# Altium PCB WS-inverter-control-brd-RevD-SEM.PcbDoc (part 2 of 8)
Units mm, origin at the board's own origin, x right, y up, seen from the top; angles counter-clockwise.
Board outline 270 x 105.92 mm, 6 copper layers (Top Layer, Int1 (Sign), Int2 (PWR), Int3 (GND), Int4 (Sign), Bottom Layer), stack 1.509 mm thick; 709 components, 375 nets, 2377 pads, 1332 vias.
Unrouted connection lines stored in the file: 55.
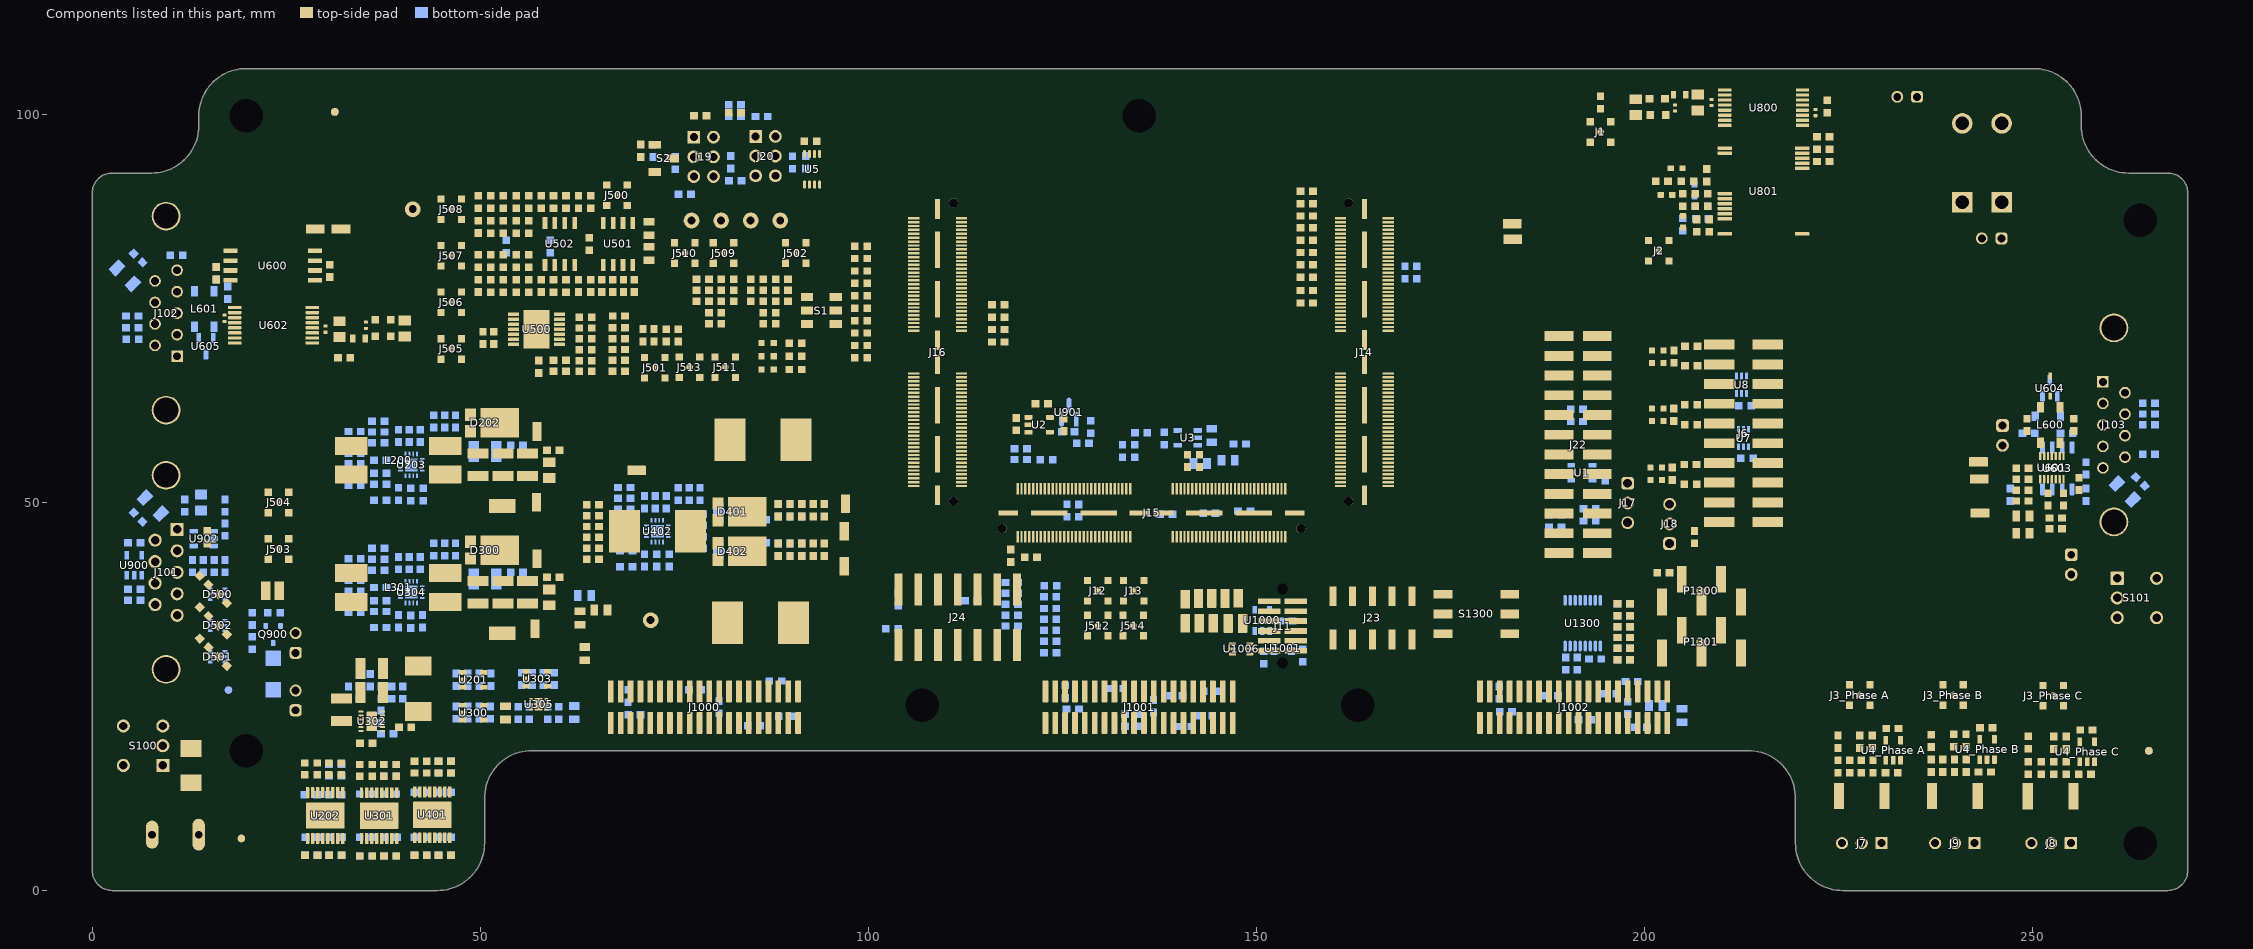
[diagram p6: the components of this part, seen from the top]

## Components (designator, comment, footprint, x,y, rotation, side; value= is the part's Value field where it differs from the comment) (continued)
R557 "CRCW06036K04FKEA" 0603#1 80.25,74.453 r180 top value=6.04k
R558 "CRCW060310K0FKEA" 0603#1 88.85,77.353 r180 top value=10.0k
R559 "CRCW060310K0FKEA" 0603#1 81.85,77.353 r180 top value=10.0k
R560 "CRCW060310K0FKEA" 0603#1 88.85,78.753 r180 top value=10.0k
R561 "CRCW060310K0FKEA" 0603#1 81.85,78.753 r180 top value=10.0k
R562 "CRCW06030000Z0EA" 0603#1 75.521,71.536 r90 top value=0
R563 "CRCW06030000Z0EA" 0603#1 118.468,38.286 r180 bottom value=0
R564 "CRCW06030000Z0EA" 0603#1 118.468,36.886 r0 bottom value=0
R565 "CRCW060347R0FKEA" 0603#1 118.468,35.486 r180 bottom value=47.0
R566 "CRCW06030000Z0EA" 0603#1 70.957,71.557 r90 top value=0
R568 "CRCW06030000Z0EA" 0603#1 191.293,60.436 r0 bottom value=0
R569 "CRCW06030000Z0EA" 0603#1 123.418,33.542 r0 bottom value=0
R570 "CRCW060347R0FKEA" 0603#1 123.443,32.136 r180 bottom value=47.0
R600 "CRCW06030000Z0EA" 0603#2 249.3,60 r90 top value=0
R601 "CRCW06030000Z0EA" 0603#2 17.443,77.036 r270 bottom value=0
R602 "CRCW060360R4FKEA" 0603#2 265,61.406 r180 bottom value=60.4
R603 "CRCW060360R4FKEA" 0603#2 5.168,71.021 r0 bottom value=60.4
R604 "CRCW060310R0FKEA" 0603#2 248.7,53 r0 top value=10.0
R605 "CRCW060360R4FKEA" 0603#2 265,62.806 r0 bottom value=60.4
R606 "CRCW060310K0FKEA" 0603#2 248.7,54.4 r0 top value=10.0k
R607 "CRCW060360R4FKEA" 0603#2 5.143,74.036 r180 bottom value=60.4
R608 "CRCW06030000Z0EA" 0603#2 255.3,60 r90 top value=0
R609 "CRCW060310R0FKEA" 0603#2 248.7,50.2 r0 top value=10.0
R610 "CRCW06030000Z0EA" 0603#2 10.843,81.836 r180 bottom value=0
R612 "CRCW06031K00FKEA" 0603#2 249.5,58.9 r0 bottom value=1.00k
R613 "CRCW060310K0FKEA" 0603#2 256.9,54.4 r90 bottom value=10.0k
R614 "CRCW060310R0FKEA" 0603#2 256.9,51 r90 bottom value=10.0
R615 "CRCW060310R0FKEA" 0603#2 247.15,51 r90 bottom value=10.0
R616 "CRCW060310R0FKEA" 0603#1 147.843,57.536 r0 bottom value=10.0
R617 "CRCW060310K0FKEA" 0603#1 248.7,51.6 r0 top value=10.0k
R618 "CRCW060310K0FKEA" 0603#1 253,46.6 r0 top value=10.0k
R619 "CRCW060310K0FKEA" 0603#1 253,48 r0 top value=10.0k
R620 "RC0603FR-0718KL" 0603#1 32.443,68.636 r0 top value=18.0k
R800 "RC0603FR-0718KL" 0603#1 194.343,101.536 r270 top value=18.0k
R804 "CRCW06030000Z0EA" 0603#1 132.743,56.636 r270 bottom value=0
R900 "CRCW0603100RFKEA" 0603#2 125.743,59.136 r0 bottom value=100
R901 "CRCW060317K8FKEA" 0603#2 17.1,46.5 r90 bottom value=17.8k
R902 "CRCW060330K1FKEA" 0603#2 17.1,49.6 r90 bottom value=30.1k
R903 "CRCW080520K0FKEA" 0805_HV#1 14,50 r270 bottom value=20.0k
R904 "CRCW060347R0FKEA" 0603#2 14.3,41.8 r90 bottom value=47.0
R905 "CRCW060310K0FKEA" 0603#2 20.6,35 r270 bottom value=10.0k
R906 "CRCW0603100RFKEA" 0603#2 20.6,31.9 r90 bottom value=100
R907 "CRCW060310K0FKEA" 0603#2 23.4,35.8 r180 bottom value=10.0k
R1000 "CRCW06030000Z0EA" 0603#2 69.031,25.056 r270 bottom value=0
R1001 "CRCW06030000Z0EA" 0603#2 125.349,25.653 r270 bottom value=0
R1002 "CRCW06030000Z0EA" 0603#2 181.271,25.5 r270 bottom value=0
R1003 "CRCW06030000Z0EA" 0603#2 69.843,22.636 r0 bottom value=0
R1004 "CRCW06030000Z0EA" 0603#2 126.343,23.386 r0 bottom value=0
R1005 "CRCW06030000Z0EA" 0603#2 182.143,23.036 r0 bottom value=0
R1006 "CRCW06030000Z0EA" 0603#2 88.029,26.999 r0 bottom value=0
R1007 "CRCW06030000Z0EA" 0603#2 144.029,25.653 r0 bottom value=0
R1008 "CRCW06030000Z0EA" 0603#2 198.343,26.936 r180 bottom value=0
R1009 "CRCW06030000Z0EA" 0603#2 89.243,22.436 r180 bottom value=0
R1010 "CRCW06030000Z0EA" 0603#2 143.499,22.522 r0 bottom value=0
R1011 "CRCW06030000Z0EA" 0603#2 199.543,21.036 r0 bottom value=0
R1012 "CRCW06030000Z0EA" 0603#1 192.3,22 r0 bottom value=0
R1013 "CRCW06030000Z0EA" 0603#1 80.743,23.636 r90 bottom value=0
R1014 "CRCW06030000Z0EA" 0603#1 136.743,23.736 r90 bottom value=0
R1015 "CRCW06030000Z0EA" 0603#1 133.869,21.145 r180 bottom value=0
R1016 "CRCW06030000Z0EA" 0603#1 133.869,22.717 r0 bottom value=0
R1017 "CRCW06030000Z0EA" 0603#1 139.689,25.117 r0 bottom value=0
R1018 "CRCW06030000Z0EA" 0603#1 195.614,25.362 r0 bottom value=0
R1019 "CRCW060310K0FKEA" 0603#1 77.675,25.855 r0 bottom value=10.0k
R1020 "CRCW060310K0FKEA" 0603#1 132.043,26.036 r180 bottom value=10.0k
R1021 "CRCW060310K0FKEA" 0603#1 188.069,25.1 r180 bottom value=10.0k
R1022 "CRCW060310K0FKEA" 0603#1 85.243,21.236 r0 bottom value=10.0k
R1023 "CRCW060310K0FKEA" 0603#1 140.82,21.13 r0 bottom value=10.0k
R1024 "CRCW060310K0FKEA" 0603#1 197.843,23.536 r270 bottom value=10.0k
R1027 "CRCW060310K0FKEA" 0603#1 138.383,48.491 r0 bottom value=10.0k
R1030 "CRCW060310K0FKEA" 0603#1 143.943,48.636 r0 bottom value=10.0k
R1034 "CRCW06030000Z0EA" 0603#1 116.743,73.884 r0 top value=0
R1036 "CRCW06030000Z0EA" 0603#1 116.743,70.684 r0 top value=0
R1040 "CRCW06030000Z0EA" 0603#1 116.743,75.484 r0 top value=0
R1042 "CRCW06030000Z0EA" 0603#1 116.743,72.284 r0 top value=0
R1300 "CRCW06031K00FKEA" 0603#2 197.343,36.936 r180 top value=1.00k
R1301 "CRCW06031K00FKEA" 0603#2 197.343,35.4 r180 top value=1.00k
R1302 "CRCW06031K00FKEA" 0603#2 197.343,34 r180 top value=1.00k
R1303 "CRCW06031K00FKEA" 0603#2 191.326,29.242 r90 bottom value=1.00k
R1304 "CRCW06030000Z0EA" 0603#2 189.843,29.236 r90 bottom value=0
R1305 "CRCW06031K00FKEA" 0603#2 197.343,29.714 r180 top value=1.00k
R1306 "CRCW06031K00FKEA" 0603#2 197.343,31.2 r180 top value=1.00k
R1307 "CRCW06031K00FKEA" 0603#2 197.343,32.6 r180 top value=1.00k
Rjldc1 "CRCW06030000Z0EA" 0603#1 127.113,48.955 r270 bottom value=0
Rjldc2 "CRCW06030000Z0EA" 0603#1 125.589,48.97 r270 bottom value=0
Rjump12v "5106" 5106#1 62.843,35.136 r270 top value=0
Rjumppre "5106" 5106#1 63.443,38.036 r180 bottom value=0
S1 "CAS-220TA" SW_CAS-220TA 93.943,74.736 r180 top
S2 "CAS-120TA" SW_CAS-120TA 73.643,94.336 r0 top
S100 "200MSP1T1B2M6QE" FP-200MSP1T1B2M6QE_PTH_SW_23MM63_8MM13-MFG -3.185,18.66 r0 top locked
S101 "200MSP1T1B2M6QE" FP-200MSP1T1B2M6QE_PTH_SW_23MM63_8MM13-MFG 273.185,37.696 r180 top locked
S1300 "219-3MST" SW_219-3MST 178.343,35.636 r180 top locked
TP1 "RCU-0C" TE_RCU 140.843,37.536 r90 top
TP2 "RCU-0C" TE_RCU 142.543,37.636 r90 top
TP3 "RCU-0C" TE_RCU 144.243,37.636 r90 top
TP4 "RCU-0C" TE_RCU 145.943,37.636 r90 top
TP5 "RCU-0C" TE_RCU 147.65,37.678 r90 top
TP6 "RCU-0C" TE_RCU 148.23,34.41 r90 top
TP7 "RCU-0C" TE_RCU 146.364,34.415 r90 top
TP8 "RCU-0C" TE_RCU 144.458,34.436 r90 top
TP9 "RCU-0C" TE_RCU 142.643,34.436 r90 top
TP10 "RCU-0C" TE_RCU 140.845,34.426 r90 top
TP100 "5000" Keystone5000 71.943,34.836 r90 top
TP101 "5000" Keystone5000 41.293,87.795 r90 top
TP200 "5015" Testpoint_Keystone_Miniature 52.8,49.55 r0 top
TP201 "RCU-0C" TE_RCU 57.3,59.15 r90 top
TP202 "RCU-0C" TE_RCU 57.243,50.036 r90 top
TP300 "5015" Testpoint_Keystone_Miniature 52.8,33.15 r180 top
TP301 "RCU-0C" TE_RCU 57.3,42.75 r90 top
TP302 "RCU-0C" TE_RCU 57.043,33.736 r90 top
TP400 "RCU-0C" TE_RCU 70.143,54.136 r180 top
TP401 "RCU-0C" TE_RCU 97.043,49.836 r270 top
TP402 "RCU-0C" TE_RCU 96.9,46.3 r90 top
TP403 "RCU-0C" TE_RCU 22.343,38.636 r90 top
TP404 "RCU-0C" TE_RCU 96.9,41.8 r90 top
TP500 "5000" Keystone5000 84.833,86.336 r90 top
TP501 "5000" Keystone5000 77.213,86.336 r90 top
TP502 "5000" Keystone5000 88.643,86.336 r90 top
TP503 "5000" Keystone5000 81.023,86.336 r90 top
TP600 "RCU-0C" TE_RCU 243.143,53.036 r0 top
TP601 "RCU-0C" TE_RCU 32.043,85.236 r180 top
TP602 "RCU-0C" TE_RCU 243.043,55.236 r180 top
TP603 "RCU-0C" TE_RCU 28.743,85.236 r180 top
TP604 "RCU-0C" TE_RCU 243.243,48.636 r0 top
TP900 "RCU-0C" TE_RCU 24.093,38.636 r90 top
TP_alert "RCU-0C" TE_RCU 182.943,85.936 r180 top
TP_voc "RCU-0C" TE_RCU 183.043,83.936 r0 top
U1 "SN74LVC1G3208DBVR" DBV0006A_N 191.943,53.836 r0 bottom
U2 "REF2033AIDDCR" DDC0005A_N 122.01,60.011 r0 top
U3 "TLV9001QDBVRQ1" DBV0005A-MFG 141.143,58.336 r180 bottom
"U4_Phase A" "TLV9001QDBVRQ1" DBV0005A-MFG 232.05,18.078 r90 top (schematic designator U4)
"U4_Phase B" "TLV9001QDBVRQ1" DBV0005A-MFG 244.15,18.178 r90 top (schematic designator U4)
"U4_Phase C" "TLV9001QDBVRQ1" DBV0005A-MFG 257.05,17.878 r90 top (schematic designator U4)
U5 "CLVC2G125IDCTRQ1" DCT0008A_N 92.743,92.936 r270 top
U7 "SN74LVC1G11IDCKRQ1" DCK0006A_N 212.773,58.299 r270 bottom
U8 "SN74LVC1G11IDCKRQ1" DCK0006A_N 212.523,65.174 r270 bottom
U201 "TPS7B6933QDBVRQ1" DBV0005A_N 49.075,27.15 r0 top
U202 "LM74202QPWPRQ1" PWP0016J_N 30,9.663 r90 top
U203 "LM5158QRTERQ1" RTE0016K-MFG 41.1,54.85 r90 bottom
U300 "TPS7B6933QDBVRQ1" DBV0005A_N 49.075,22.925 r0 top
U301 "LM74202QPWPRQ1" PWP0016J_N 36.957,9.643 r90 top
U302 "LM63635DQDRRRQ1" DRR0012E-MFG 36,21.8 r180 top
U303 "TLV73333PQDBVRQ1" DBV0005A_N 57.3,27.275 r0 top
U304 "LM5158QRTERQ1" RTE0016K-MFG 41.1,38.45 r90 bottom
U305 "TLV73333PQDRVRQ1" DRV0006A 57.5,24 r180 top
U401 "LM74202QPWPRQ1" PWP0016J_N 43.8,9.743 r90 top
U402 "LM5157QRTERQ1" RTE0016K 72.8,46.3 r90 bottom
U500 "ALM2403QPWPRQ1" PWP0014H_N 57.238,72.311 r180 top
U501 "OPA2991IDR" D0008A-MFG 67.738,83.311 r90 top
U502 "OPA2991IDR" D0008A-MFG 60.238,83.311 r90 top
U600 "ISO1042QDWVRQ1" DWV0008A-MFG 23.243,80.536 r180 top
U601 "TCAN1043ADYYRQ1" DYY0014A-MFG 252.5,54.5 r90 top
U602 "UCC33421-Q1" DWX0016A-MFG 23.343,72.836 r180 top
U603 "TLIN1021ADRQ1" D0008A-MFG 253.2,54.4 r90 bottom
U604 "ESD2CAN24DBZR" DBZ0003A-MFG 252.243,64.736 r90 bottom
U605 "ESD2CAN24DBZR" DBZ0003A-MFG 14.643,70.136 r270 bottom
U800 "UCC33421-Q1" DWX0016A-MFG 215.35,100.878 r0 top
U801 "AMC038x" DFX0015-MFG 215.343,90.136 r180 top
U900 "TPS7B4255QDBVRQ1" DBV0005A-MFG 5.4,41.9 r90 bottom
U901 "TMP235AEDBZRQ1" FP-DBZ0003A-IPC_A 125.843,61.636 r90 bottom
U902 "TLV9001QDBVRQ1" DBV0005A-MFG 14.343,45.353 r180 bottom
U1000 "SN74AHC1G32DBVR" DBV0005A_N 150.744,34.813 r90 bottom
U1001 "SN74LVC1G332DCKR" DCK0006A_N 153.394,31.188 r0 bottom
U1006 "SN74LVC1G332DCKR" DCK0006A_N 148.043,31.136 r180 top
U1300 "TXB0106PWR" PW0016A_N 192.05,34.45 r90 bottom

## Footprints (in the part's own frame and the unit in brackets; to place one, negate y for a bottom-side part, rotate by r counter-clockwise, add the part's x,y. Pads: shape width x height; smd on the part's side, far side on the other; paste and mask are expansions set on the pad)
0603#1 [mm] "0603 from SM-752 data"
  rect 1x0.95 smd: 1(-0.8,0) 2(0.8,0)
  silkscreen extent -1.52,-0.69 1.52,0.69, body extent -0.87,-0.47 0.87,0.47, height 1
0603#2 [mm] "0603 from SM-752 data"
  rrect1% 1x0.95 smd: 1(-0.8,0) 2(0.8,0)
  silkscreen extent -1.52,-0.69 1.52,0.69, body extent -0.87,-0.47 0.87,0.47, height 1
0805_HV#1 [mil] "0805 with 30mil clearance between pads"
  rrect1% 50x63 smd: 1(-40,0) 2(40,0)
  silkscreen extent -74,-40 74,40, body extent -43,-29 43,29, height 57
0805_HV#2 [mil] "0805 with 30mil clearance between pads"
  rect 50x63 smd: 1(-40,0) 2(40,0)
  silkscreen extent -74,-40 74,40, body extent -43,-29 43,29, height 57
1206 [mm] "1206 from SM-752 data"
  rrect1% 1.3x1.85 smd: 1(-1.45,0) 2(1.45,0)
  silkscreen extent -2.4,-1.21 2.4,1.21, body extent -1.7,-0.9 1.7,0.9, height 1.35
1206_190 [mm] "1206_190"
  rrect1% 1.1x1.6 smd: 1(-1.7,0) 2(1.7,0)
  silkscreen extent -0.9,-1 0.9,1, body extent -1.75,-0.95 1.75,0.95, height 1.9
1210 [mm] "1210 from SM-752 data"
  rrect1% 1.3x2.7 smd: 1(-1.45,0) 2(1.45,0)
  silkscreen extent -2.32,-1.57 2.32,1.57, body extent -1.7,-1.35 1.7,1.35, height 1.35
1210_270#1 [mm] "1210"
  rrect1% 1.3x2.7 smd: 1(-1.45,0) 2(1.45,0)
  silkscreen extent -2.32,-1.57 2.32,1.57, body extent -1.7,-1.35 1.7,1.35, height 2.7
1210_270#2 [mm] "1210"
  rect 1.3x2.7 smd: 1(-1.45,0) 2(1.45,0)
  silkscreen extent -2.32,-1.57 2.32,1.57, body extent -1.7,-1.35 1.7,1.35, height 2.7
2512 [mm] "Chip Resistor, Body 6.3x3.2mm, IPC Medium Density"
  rect 1.3x3.4 smd: 1(-2.95,0) 2(2.95,0)
  silkscreen extent -1.9,-1.6 1.9,1.6, body extent -3.22,-1.67 3.22,1.67, height 0.71
5106#1 [mm] "Keystone"
  rect 0.99x1.4 smd: 1(-0.85,0) 2(0.88,0)
  silkscreen extent -1.63,-0.97 1.65,0.97, body extent -1.06,-0.69 1.06,0.69, height 0.84
5106#2 [mm] "Keystone"
  rrect1% 0.99x1.4 smd: 1(-0.85,0) 2(0.88,0)
  silkscreen extent -1.63,-0.97 1.65,0.97, body extent -1.06,-0.69 1.06,0.69, height 0.84
ACT45B [mm] "SMD, 4-Leads, Body 4.7 x 3.7 mm"
  rrect1% 1.35x0.9 smd: 1(-2.275,1.25) 2(-2.275,-1.25) 3(2.275,-1.25) 4(2.275,1.25)
  silkscreen extent -2.35,-1.7 2.35,2, body extent -2.35,-1.7 2.35,1.7, height 3
CONN_TSM-105-01-T-DV-P [mil]
  rect 36x100 smd: 1(-200,-110) 2(-200,110) 3(-100,-110) 4(-100,110) 5(0,-110) 6(0,110) 7(100,-110) 8(100,110) 9(200,-110) 10(200,110)
  silkscreen extent -250,-160 250,100, body extent -250,-145 250,145, height 380
CUI_PJ-037AH [mm] "Power Jack, 2mm, R/A, TH"
  oval 4.1x1.6 hole 1 slot 3.5 at 0 deg: 1(0,3)
  oval 3.6x1.6 hole 1 slot 3 at 0 deg: 2(0,-3)
  silkscreen extent -4.5,-10.3 4.5,3.8, body extent -4.5,-10.7 4.5,3.8, height 11
D0008A-MFG [mm]
  rrect17% 1.55x0.6 smd paste+0 mask+0: 1(-2.7,1.905) 2(-2.7,0.635) 3(-2.7,-0.635) 4(-2.7,-1.905) 5(2.7,-1.905) 6(2.7,-0.635) 7(2.7,0.635) 8(2.7,1.905)
  silkscreen extent -3.35,-2.5 1.5,3, body extent -3,-2.45 3,2.45, height 1.75
DBV0005A-MFG [mm]
  rrect17% 1.1x0.6 smd paste+0 mask+0: 1(-1.3,0.95) 2(-1.3,0) 3(-1.3,-0.95) 4(1.3,-0.95) 5(1.3,0.95)
  silkscreen extent -0.38,-1.53 0.87,1.53, body extent -1.4,-1.45 1.4,1.45, height 1.45
DBV0005A_N [mm] "SOT23, 5-Leads, Body 2.9x1.6mm, Pitch 0.95mm, Lead Span 2.8mm, IPC Medium Density"
  rrect17% 1x0.6 smd: 1(-1.375,0.95) 2(-1.375,0) 3(-1.375,-0.95) 4(1.375,-0.95) 5(1.375,0.95)
  silkscreen extent -1.63,-1.55 0.38,1.55, body extent -1.42,-1.46 1.42,1.46, height 1.09
DBV0006A_N [mm] "SOT23, 6-Leads, Body 2.9x1.6mm, Pitch 0.95mm, Lead Span 2.8mm, IPC Medium Density"
  rrect17% 1x0.6 smd: 1(-1.375,0.95) 2(-1.375,0) 3(-1.375,-0.95) 4(1.375,-0.95) 5(1.375,0) 6(1.375,0.95)
  silkscreen extent -1.68,-1.55 0.5,1.55, body extent -1.42,-1.46 1.42,1.46, height 1.12
DBZ0003A-MFG [mm]
  rrect17% 1.3x0.6 smd paste+0 mask+0: 1(-1.05,0.95) 2(-1.05,-0.95) 3(1.05,0)
  silkscreen extent -0.7,-1.52 0.7,1.52, body extent -1.18,-1.46 1.18,1.46, height 1.12
DCK0006A_N [mm] "SOT23, 6-Leads, Body 2x1.3mm, Pitch 0.65mm, Lead Span 2.1mm, IPC Medium Density"
  rrect25% 0.85x0.4 smd: 1(-1.125,0.65) 2(-1.125,0) 3(-1.125,-0.65) 4(1.125,-0.65) 5(1.125,0) 6(1.125,0.65)
  silkscreen extent -1.5,-1.09 0.51,1.09, body extent -1.14,-1 1.14,1, height 0.95
DCT0008A_N [mm] "TSOP, 8-Leads, Body 3x2.8mm, Pitch 0.65mm, IPC Medium Density"
  oval 1.05x0.4 smd: 1(-1.975,0.975) 2(-1.975,0.325) 3(-1.975,-0.325) 4(-1.975,-0.975) 5(1.975,-0.975) 6(1.975,-0.325) 7(1.975,0.325) 8(1.975,0.975)
  silkscreen extent -2.32,-1.57 0.6,1.58, body extent -2.01,-1.47 2.01,1.48, height 1.3
DDC0005A_N [mm]
  rrect17% 1x0.6 smd: 1(-1.375,0.95) 2(-1.375,0) 3(-1.375,-0.95) 4(1.375,-0.95) 5(1.375,0.95)
  silkscreen extent -1.25,-1.52 0.88,1.57, body extent -1.41,-1.45 1.41,1.45, height 1.1
DFX0015-MFG [mm]
  rrect22% 1.85x0.45 smd paste+0 mask+0: 1(-4.975,5.525) 2(-4.975,-2.925) 3(-4.975,-3.575) 4(-4.975,-4.225) 5(-4.975,-4.875) 6(-4.975,-5.525) 7(4.975,-5.525) 8(4.975,-4.875) 9(4.975,0.325) 10(4.975,0.975) 11(4.975,1.625) 12(4.975,2.275) 13(4.975,2.925) 14(4.975,3.575) 15(4.975,5.525)
  silkscreen extent -6.58,-6.47 3.5,6.47, body extent -6,-6.72 6,6.72, height 0.25
DRR0012E-MFG [mm]
  rrect40% 0.62x0.25 smd paste+0 mask+0: 1(-1.39,1.25) 2(-1.39,0.75) 3(-1.39,0.25) 4(-1.39,-0.25) 5(-1.39,-0.75) 6(-1.39,-1.25) 7(1.39,-1.25) 8(1.39,-0.75) 9(1.39,-0.25) 10(1.39,0.25) 11(1.39,0.75) 12(1.39,1.25)
  rrect8% 1.3x2.5 smd paste-1000 mask+0: 13(0,0)
  body extent -1.8,-1.65 1.8,1.65, height 0.25
DRV0006A [mm] "SON, 6-Leads, Body 2x2mm, Pitch 0.65mm, Thermal Pad 1.6x1mm, TI Recommended"
  rrect33% 0.45x0.3 smd: 1(-0.975,0.65) 2(-0.975,0) 3(-0.975,-0.65) 4(0.975,-0.65) 5(0.975,0) 6(0.975,0.65)
  rrect14% 1x0.7 on Top Paste: 7(0,0.45) 7(0,-0.45)
  rrect10% 1x1.6 smd paste-0.5: 7(0,0)
  silkscreen extent -1.05,-1.2 1.05,1.2, body extent -1.05,-1.05 1.05,1.05, height 0.81
DWV0008A-MFG [mm]
  rrect17% 1.8x0.6 smd paste+0 mask+0: 1(-5.45,1.905) 2(-5.45,0.635) 3(-5.45,-0.635) 4(-5.45,-1.905) 5(5.45,-1.905) 6(5.45,-0.635) 7(5.45,0.635) 8(5.45,1.905)
  silkscreen extent -5.72,-2.98 3.8,2.98, body extent -6.45,-3.22 6.45,3.22, height 0.25
DWX0016A-MFG [mm]
  rrect24% 1.7x0.41 smd paste+0 mask+0: 1(-5,2.275) 2(-5,1.625) 3(-5,0.975) 4(-5,0.325) 5(-5,-0.325) 6(-5,-0.975) 7(-5,-1.625) 8(-5,-2.275) 9(5,-2.275) 10(5,-1.625) 11(5,-0.975) 12(5,-0.325) 13(5,0.325) 14(5,0.975) 15(5,1.625) 16(5,2.275)
  silkscreen extent -6.53,-2.98 3.8,2.98, body extent -5.95,-3.22 5.95,3.22, height 0.25
DYF0002A-MFG [mm]
  rrect20% 0.9x0.5 smd paste+0 mask+0: 1(-1.3,0) 2(1.3,0)
  silkscreen extent -1.55,-0.7 0.9,0.92, body extent -1.85,-0.8 1.85,0.8, height 0.25
DYY0014A-MFG [mm]
  rrect33% 1.05x0.3 smd paste+0 mask+0: 1(-1.5,1.5) 2(-1.5,1) 3(-1.5,0.5) 4(-1.5,0) 5(-1.5,-0.5) 6(-1.5,-1) 7(-1.5,-1.5) 8(1.5,-1.5) 9(1.5,-1) 10(1.5,-0.5) 11(1.5,0) 12(1.5,0.5) 13(1.5,1) 14(1.5,1.5)
  silkscreen extent -2.72,-2.15 1.05,2.15, body extent -2.12,-2.4 2.12,2.4, height 0.25
FCC_disclaimer [mm]
Fiducial10-20 [mm]
  round 1 smd mask+0.5: 1(0,0)
  Top Layer keep-out circle w1.178: c0,0 r0.5
FP-200MSP1T1B2M6QE_PTH_SW_23MM63_8MM13-MFG [mm]
  rrect6% 1.69x1.69 hole 1.09 paste-2539.97 mask+0: 1(12.265,-2.54)
  round 1.69 hole 1.09 paste-2539.97 mask+0: 2(12.265,0) 3(12.265,2.54) 4(7.185,2.54) 5(7.185,-2.54)
  silkscreen extent 4.23,-4.19 13.79,4.19, body extent -12.29,-4.29 13.21,4.29, height 0.25
FP-06035C100KAT2A_0603-MFG [mm]
  rrect13% 0.8x0.75 smd paste+0 mask+0: 1(-0.75,0) 2(0.75,0)
  silkscreen extent -0.87,-0.77 0.87,0.77, body extent -1.25,-0.58 1.25,0.58, height 0.25
FP-22232031_HDR3-MFG [mm]
  rrect6% 1.57x1.57 hole 1.02 paste-2539.97 mask+0: 1(-2.54,0.075)
  round 1.57 hole 1.02 paste-2539.97 mask+0: 2(0,0.075) 3(2.54,0.075)
  silkscreen extent -4.45,-3.3 3.86,3.3, body extent -3.96,-3.4 3.96,3.4, height 0.25
FP-618009231221_CONN_DSUB_30MM8_18MM4-MFG [mm]
  rrect6% 1.69x1.69 hole 1.09 paste-2539.97 mask+0: 1(-5.54,7.72)
  round 1.69 hole 1.09 paste-2539.97 mask+0: 2(-2.77,7.72) 3(0,7.72) 4(2.77,7.72) 5(5.54,7.72) 6(-4.155,4.88) 7(-1.385,4.88) 8(1.385,4.88) 9(4.155,4.88)
  round 3.7 hole 3.2 paste-2539.97 mask+0: 10(-12.5,6.3) 11(12.5,6.3)
  silkscreen extent -15.5,-2.44 15.5,9.92, body extent -15.6,-9.4 15.6,9.4, height 0.25
FP-DBZ0003A-IPC_A [mm]
  rect 1.874x0.612 smd paste+0 mask+0: 1(-0.935,0.95)
  rrect100% 1.874x0.612 smd paste+0 mask+0: 2(-0.935,-0.95) 3(0.935,0)
  silkscreen extent 0,-1.46 0.65,1.46, body extent -1.18,-1.46 1.18,1.46, height 1.12
FP-ESHF-120-01-L-D-SM_HDR40-MFG [mm]
  rrect14% 0.74x2.795 smd paste+0 mask+0: 1(-12.065,-2.288) 2(-12.065,1.777) 3(-10.795,-2.288) 4(-10.795,1.777) 5(-9.525,-2.288) 6(-9.525,1.777) 7(-8.255,-2.288) 8(-8.255,1.777) 9(-6.985,-2.288) 10(-6.985,1.777) 11(-5.715,-2.288) 12(-5.715,1.777) 13(-4.445,-2.288) 14(-4.445,1.777) 15(-3.175,-2.288) 16(-3.175,1.777) 17(-1.905,-2.288) 18(-1.905,1.777) 19(-0.635,-2.288) 20(-0.635,1.777) 21(0.635,-2.288) 22(0.635,1.777) 23(1.905,-2.288) 24(1.905,1.777) 25(3.175,-2.288) 26(3.175,1.777) 27(4.445,-2.288) 28(4.445,1.777) 29(5.715,-2.288) 30(5.715,1.777) 31(6.985,-2.288) 32(6.985,1.777) 33(8.255,-2.288) 34(8.255,1.777) 35(9.525,-2.288) 36(9.525,1.777) 37(10.795,-2.288) 38(10.795,1.777) 39(12.065,-2.288) 40(12.065,1.777)
  silkscreen extent -17.85,-4.38 17.85,2.86, body extent -17.95,-3.78 17.95,3.27, height 0.25
FP-GCM155R71H153KA55D_0402-MFG [mm]
  rrect25% 0.4x0.5 smd paste+0 mask+0: 1(-0.4,0) 2(0.4,0)
  silkscreen extent -0.53,-0.63 0.53,0.63, body extent -0.7,-0.38 0.7,0.38, height 0.25
FP-HPM-03-01-T-S_HDR3-MFG [mm]
  rrect4% 2.65x2.65 hole 1.75 paste-2539.97 mask+0: 1(-5.08,0)
  round 2.65 hole 1.75 paste-2539.97 mask+0: 3(5.08,0)
  silkscreen extent -8.5,-3.24 7.8,3.24, body extent -7.62,-3.18 7.62,3.18, height 14.73
FP-IPL1-110-02-L-D-K-0 [mm]
  rect 3.94x1.27 smd paste+0 mask+0: 1(-3.11,11.43) 2(-3.11,8.89) 3(-3.11,6.35) 4(-3.11,3.81) 5(-3.11,1.27) 6(-3.11,-1.27) 7(-3.11,-3.81) 8(-3.11,-6.35) 9(-3.11,-8.89) 10(-3.11,-11.43) 11(3.11,11.43) 12(3.11,8.89) 13(3.11,6.35) 14(3.11,3.81) 15(3.11,1.27) 16(3.11,-1.27) 17(3.11,-3.81) 18(3.11,-6.35) 19(3.11,-8.89) 20(3.11,-11.43)
  silkscreen extent -5.76,-13.61 3.84,13.61, body extent -4.79,-13.46 4.79,13.46, height 8.76
FP-LCMGA160808T601RG_0603-MFG [mm] "Recommended Land Pattern"
  rrect10% 1x1 smd paste+0 mask+0: 1(-1,0) 2(1,0)
  silkscreen extent -0.13,-0.45 0.13,0.45, body extent -1.6,-0.6 1.6,0.6, height 0.25
IEC_HighVoltage_Large [mm]
  silkscreen extent -11.05,-8.94 11.05,10.2
IHLP-2525CZ-5A [mil] "Vishay Dale recommended land pattern"
  rect 95x135 smd: 1(-114.96,0) 2(114.96,0)
  silkscreen extent -145,-136 145,136, body extent -143,-134 143,134, height 118
Keystone5000 [mil] "For Keystone 500x miniature loop terminals"
  round 80 hole 40: 1(0,0)
  silkscreen extent -52,-52 52,52, body extent -49,-49 49,49, height 182
Label_650x200 [mil] "Thermal Transfer Label"
  round 1 on Mech13: 0(0,0)
  silkscreen extent -325,-100 325,100, body extent -325,-100 325,100, height 1
Molex_73415-2063 [mm] "MMCX JACK, 1 Pos, Body 3.45x3.45mm, SMT"
  round 0.89 smd: 1(0,0)
  rect 0.94x0.94 smd: 2(-1.32,1.32) 3(1.32,1.32) 4(1.32,-1.32) 5(-1.32,-1.32)
  silkscreen extent -1.8,-1.8 1.8,1.8, body extent -1.8,-1.8 1.8,1.8, height 5.15
MSD1514 [mm] "SMD, 4-Leads, Body 15x15mm"
  rrect1% 4.2x2.3 smd: 1(-6.05,1.85) 2(-6.05,-1.85) 3(6.05,-1.85) 4(6.05,1.85)
  silkscreen extent -8.1,-7.75 7.75,7.75, body extent -7.81,-7.75 7.79,7.75, height 14.2
MSS1278T [mm] "Coilcraft recommended land pattern.  Document 598-2 rev 10/20/08"
  rrect1% 4x5.5 smd: 1(-4.25,0) 2(4.25,0)
  silkscreen extent -6.2,-6.2 6.2,6.2, body extent -6.15,-6.15 6.15,6.15, height 8.1
Net-Tie_10mil [mil] "10mil net tie, no solder mask opening, no solder paste"
  rrect1% 10x10 smd paste-5 mask-5: 1(-10,0) 2(10,0)
  Top Layer region: -6,5 6,5 6,-5 -6,-5
PW0016A_N [mm] "TSOP, 16-Leads, Body 5x4.4mm, Pitch 0.65mm, IPC Medium Density"
  oval 1.4x0.45 smd: 1(-2.95,2.275) 2(-2.95,1.625) 3(-2.95,0.975) 4(-2.95,0.325) 5(-2.95,-0.325) 6(-2.95,-0.975) 7(-2.95,-1.625) 8(-2.95,-2.275) 9(2.95,-2.275) 10(2.95,-1.625) 11(2.95,-0.975) 12(2.95,-0.325) 13(2.95,0.325) 14(2.95,0.975) 15(2.95,1.625) 16(2.95,2.275)
  silkscreen extent -3.5,-2.55 1.85,2.75, body extent -3.21,-2.5 3.21,2.5, height 1
PWP0014H_N [mm] "HTSSOP-14"
  rrect22% 1.4x0.45 smd: 1(-2.95,1.95) 2(-2.95,1.3) 3(-2.95,0.65) 4(-2.95,0) 5(-2.95,-0.65) 6(-2.95,-1.3) 7(-2.95,-1.95) 8(2.95,-1.95) 9(2.95,-1.3) 10(2.95,-0.65) 11(2.95,0) 12(2.95,0.65) 13(2.95,1.3) 14(2.95,1.95)
  rrect6% 3.4x5 smd paste-2 mask-2: 15(0,0)
  silkscreen extent -3.47,-2.65 1.7,2.65, body extent -3.21,-2.5 3.21,2.5, height 1
PWP0016J_N [mm] "TSOP, 16-Leads, Body 5x4.4mm, Pitch 0.65mm, Exposed Pad, IPC Medium Density"
  rrect22% 1.4x0.45 smd: 1(-2.95,2.275) 2(-2.95,1.625) 3(-2.95,0.975) 4(-2.95,0.325) 5(-2.95,-0.325) 6(-2.95,-0.975) 7(-2.95,-1.625) 8(-2.95,-2.275) 9(2.95,-2.275) 10(2.95,-1.625) 11(2.95,-0.975) 12(2.95,-0.325) 13(2.95,0.325) 14(2.95,0.975) 15(2.95,1.625) 16(2.95,2.275)
  rrect6% 3.4x5 smd paste-1.7 mask-1.7: 17(0,0)
  rrect4% 2.46x3.55 on Top Paste: 17(0,0)
  rrect4% 2.46x3.55 on Top Solder: 17(0,0)
  silkscreen extent -3.55,-2.55 1.5,2.75, body extent -3.2,-2.5 3.2,2.5, height 1.13
RTE0016K [mm] "WQFN-16"
  rrect42% 0.6x0.24 smd paste+0: 1(-1.4,0.75) 2(-1.4,0.25) 3(-1.4,-0.25) 4(-1.4,-0.75) 9(1.4,-0.75) 10(1.4,-0.25) 11(1.4,0.25) 12(1.4,0.75)
  rrect42% 0.24x0.6 smd paste+0: 5(-0.75,-1.4) 6(-0.25,-1.4) 7(0.25,-1.4) 8(0.75,-1.4) 13(0.75,1.4) 14(0.25,1.4) 15(-0.25,1.4) 16(-0.75,1.4)
  rrect6% 1.66x1.66 smd paste-0.075: 17(0,0)
  silkscreen extent -1.86,1.26 -1.79,1.34, body extent -1.5,-1.5 1.5,1.5, height 0.8
RTE0016K-MFG [mm]
  rrect42% 0.6x0.24 smd paste+0 mask+0: 1(-1.4,0.75) 2(-1.4,0.25) 3(-1.4,-0.25) 4(-1.4,-0.75) 9(1.4,-0.75) 10(1.4,-0.25) 11(1.4,0.25) 12(1.4,0.75)
  rrect42% 0.24x0.6 smd paste+0 mask+0: 5(-0.75,-1.4) 6(-0.25,-1.4) 7(0.25,-1.4) 8(0.75,-1.4) 13(0.75,1.4) 14(0.25,1.4) 15(-0.25,1.4) 16(-0.75,1.4)
  rrect6% 1.66x1.66 smd paste-1000 mask+0: 17(0,0)
  silkscreen extent -1.77,-1.58 1.58,2.13, body extent -1.5,-1.5 1.5,1.5, height 0.8
SAMTEC_QTH-060-01-L-D-A [mm] "SMD, 60x2 Position, Body 40.01x5.97mm"
  rect 0.305x1.45 smd mask+0.045: 1(-17.25,3.086) 2(-17.25,-3.086) 3(-16.75,3.086) 4(-16.75,-3.086) 5(-16.25,3.086) 6(-16.25,-3.086) 7(-15.75,3.086) 8(-15.75,-3.086) 9(-15.25,3.086) 10(-15.25,-3.086) 11(-14.75,3.086) 12(-14.75,-3.086) 13(-14.25,3.086) 14(-14.25,-3.086) 15(-13.75,3.086) 16(-13.75,-3.086) 17(-13.25,3.086) 18(-13.25,-3.086) 19(-12.75,3.086) 20(-12.75,-3.086) 21(-12.25,3.086) 22(-12.25,-3.086) 23(-11.75,3.086) 24(-11.75,-3.086) 25(-11.25,3.086) 26(-11.25,-3.086) 27(-10.75,3.086) 28(-10.75,-3.086) 29(-10.25,3.086) 30(-10.25,-3.086) 31(-9.75,3.086) 32(-9.75,-3.086) 33(-9.25,3.086) 34(-9.25,-3.086) 35(-8.75,3.086) 36(-8.75,-3.086) 37(-8.25,3.086) 38(-8.25,-3.086) 39(-7.75,3.086) 40(-7.75,-3.086) 41(-7.25,3.086) 42(-7.25,-3.086) 43(-6.75,3.086) 44(-6.75,-3.086) 45(-6.25,3.086) 46(-6.25,-3.086) 47(-5.75,3.086) 48(-5.75,-3.086) 49(-5.25,3.086) 50(-5.25,-3.086) 51(-4.75,3.086) 52(-4.75,-3.086) 53(-4.25,3.086) 54(-4.25,-3.086) 55(-3.75,3.086) 56(-3.75,-3.086) 57(-3.25,3.086) 58(-3.25,-3.086) 59(-2.75,3.086) 60(-2.75,-3.086) 61(2.75,3.086) 62(2.75,-3.086) 63(3.25,3.086) 64(3.25,-3.086) 65(3.75,3.086) 66(3.75,-3.086) 67(4.25,3.086) 68(4.25,-3.086) 69(4.75,3.086) 70(4.75,-3.086) 71(5.25,3.086) 72(5.25,-3.086) 73(5.75,3.086) 74(5.75,-3.086) 75(6.25,3.086) 76(6.25,-3.086) 77(6.75,3.086) 78(6.75,-3.086) 79(7.25,3.086) 80(7.25,-3.086) 81(7.75,3.086) 82(7.75,-3.086) 83(8.25,3.086) 84(8.25,-3.086) 85(8.75,3.086) 86(8.75,-3.086) 87(9.25,3.086) 88(9.25,-3.086) 89(9.75,3.086) 90(9.75,-3.086) 91(10.25,3.086) 92(10.25,-3.086) 93(10.75,3.086) 94(10.75,-3.086) 95(11.25,3.086) 96(11.25,-3.086) 97(11.75,3.086) 98(11.75,-3.086) 99(12.25,3.086) 100(12.25,-3.086) 101(12.75,3.086) 102(12.75,-3.086) 103(13.25,3.086) 104(13.25,-3.086) 105(13.75,3.086) 106(13.75,-3.086) 107(14.25,3.086) 108(14.25,-3.086) 109(14.75,3.086) 110(14.75,-3.086) 111(15.25,3.086) 112(15.25,-3.086) 113(15.75,3.086) 114(15.75,-3.086) 115(16.25,3.086) 116(16.25,-3.086) 117(16.75,3.086) 118(16.75,-3.086) 119(17.25,3.086) 120(17.25,-3.086)
  rect 2.54x0.64 smd: A1(-18.44,0) A4(-1.55,0) A5(1.56,0) A8(18.45,0)
  rect 4.7x0.64 smd: A2(-13.17,0) A3(-6.82,0) A6(6.83,0) A7(13.18,0)
  round 1.15 hole 1.15 unplated mask+0: MH1(-19.24,2.03) MH2(19.24,2.03)
  silkscreen extent -20,-2.99 20,2.99, body extent -20.07,-3.56 19.94,3.56, height 4.32
Samtec_TFM-106-02-x-D-A [mm] "Header(Shrouded), 1.27mm, 6x2, SMT"
  rect 2.92x0.74 smd: 1(-1.715,3.175) 2(1.715,3.175) 3(-1.715,1.905) 4(1.715,1.905) 5(-1.715,0.635) 6(1.715,0.635) 7(-1.715,-0.635) 8(1.715,-0.635) 9(-1.715,-1.905) 10(1.715,-1.905) 11(-1.715,-3.175) 12(1.715,-3.175)
  round 0 hole 1.42 unplated: MH1(0,4.765) MH2(0,-4.765)
  silkscreen extent -3.2,-5.4 2.86,5.4, body extent -2.98,-5.4 2.98,5.4, height 5.74
Samtec_TSM-112-01-x-DV [mm] "Header, 2.54mm, 12x2, SMT"
  rect 3.68x1.27 smd: 1(-2.475,13.97) 2(2.475,13.97) 3(-2.475,11.43) 4(2.475,11.43) 5(-2.475,8.89) 6(2.475,8.89) 7(-2.475,6.35) 8(2.475,6.35) 9(-2.475,3.81) 10(2.475,3.81) 11(-2.475,1.27) 12(2.475,1.27) 13(-2.475,-1.27) 14(2.475,-1.27) 15(-2.475,-3.81) 16(2.475,-3.81) 17(-2.475,-6.35) 18(2.475,-6.35) 19(-2.475,-8.89) 20(2.475,-8.89) 21(-2.475,-11.43) 22(2.475,-11.43) 23(-2.475,-13.97) 24(2.475,-13.97)
  silkscreen extent -1.75,-15.24 1.65,15.33, body extent -3.85,-15.24 3.85,15.24, height 9.65
Samtec_TSW-102-08-x-S [mm] "Header, 2.54mm, 2x1, TH"
  rrect50% 1.53x1.53 hole 1.02: 1(-1.27,0)
  round 1.53 hole 1.02: 2(1.27,0)
  silkscreen extent -2.67,-1.27 2.54,1.7, body extent -2.67,-1.27 2.54,1.27, height 8.38
SMA [mm] "Molded Diode, 2-Leads, Body 4.3x2.6mm, IPC Medium Density, based on OnSemi component dimensions and land pattern"
  rrect1% 2x2 smd: 1(-2,0) 2(2,0)
  silkscreen extent -3.66,-1.57 2.79,1.57, body extent -2.6,-1.3 2.6,1.3, height 2.42
SMB-Bi [mm] "Molded Diode, 2-Leads, Body 5.4x3.6mm, IPC Medium Density, based on OnSemi component dimensions"
  rrect1% 2.159x2.743 smd: 1(-2.21,0) 2(2.21,0)
  silkscreen extent -3.18,-1.99 3.18,1.99, body extent -2.65,-1.85 2.65,1.85, height 2.26
SMTC-TSM-105-01-X-SV [mm] "Single Row SMT Assembly, 5 Pins, Vertical, 2.54mm Pitch, Male"
  rect 1.27x3.43 smd: 1(-5.08,1.46) 2(-2.54,-1.46) 3(0,1.46) 4(2.54,-1.46) 5(5.08,1.46)
  silkscreen extent -7.11,-1.27 6.35,1.4, body extent -6.35,-2.45 6.35,2.45, height 9.65
SOD-123 [mm] "On Semi recommended land pattern"
  rrect1% 0.915x1.22 smd: 1(-1.637,0) 2(1.637,0)
  silkscreen extent -2.58,-1.16 2.03,1.17, body extent -1.93,-0.9 1.93,0.9, height 1.35
SOT1289 [mm] "CFP15, Nexperia recommended land pattern"
  rrect1% 1.6x1.44 smd paste-0.8 mask+0.1: 1(-1.065,2.78) 2(1.065,2.78)
  rrect1% 3.8x4.96 smd paste-2.48 mask+0.1: 3(0,-1.02)
  body extent -2.15,-3.25 2.15,3.25, height 0.79
SOT-23L [mm] "SOT23, 3-Leads, Body 2.9x1.3mm, Pitch 0.95mm, Lead Span 2.5mm, IPC High Density"
  rrect50% 0.8x0.6 smd: 1(-1.1,0.95) 2(-1.1,-0.95) 3(1.1,0)
  silkscreen extent -1.5,-1.5 0.7,1.5, body extent -1.16,-1.45 1.21,1.45, height 1
SOT-363 [mm]
  rrect1% 0.6x0.42 smd mask+0.051: 1(-0.95,0.65) 2(-0.95,0) 3(-0.95,-0.65) 4(0.95,-0.65) 5(0.95,0) 6(0.95,0.65)
  silkscreen extent -0.38,-1.02 0.38,1.02, body extent -1.1,-1.1 1.1,1.1, height 1.12
SULLINS_PEC03DAAN [mm] "SULLINS"
  rect 1.65x1.65 hole 1.016 mask+0: 1(-2.54,-1.27)
  round 1.65 hole 1.016 mask+0: 2(-2.54,1.27) 3(0,-1.27) 4(0,1.27) 5(2.54,-1.27) 6(2.54,1.27)
  silkscreen extent -4.06,-2.79 3.81,2.54, body extent -3.81,-2.54 3.81,2.54, height 8.38
Sullins_SBH11-xxxC-D07-SM-BK [mm] "Header(shrouded), 2.54mm, 7x2, SMT"
  rrect10% 4.15x1 smd: 1(-3.535,7.62) 2(3.615,7.62) 3(-3.535,5.08) 4(3.615,5.08) 5(-3.535,2.54) 6(3.615,2.54) 7(-3.535,0) 8(3.615,0) 9(-3.535,-2.54) 10(3.615,-2.54) 11(-3.535,-5.08) 12(3.615,-5.08) 13(-3.535,-7.62) 14(3.615,-7.62)
  silkscreen extent -5,-12.64 4.7,12.64, body extent -5.15,-12.64 5.15,12.64, height 10.62
SW_219-3MST [mm] "SMD, 6-Leads, Body 6.7x9.09mm, Pitch 2.54mm"
  rect 2.44x1.13 smd: 1(-4.3,2.54) 2(-4.3,0) 3(-4.3,-2.54) 4(4.3,-2.54) 5(4.3,0) 6(4.3,2.54)
  silkscreen extent -3.35,-4.54 3.35,4.54, body extent -4.95,-4.55 4.96,4.55, height 4.3
SW_CAS-120TA [mm] "COPAL ELECTRONICS"
  rect 1.6x1 smd: 1(-1.15,1.75) 2(1.15,0) 3(-1.15,-1.75)
  silkscreen extent -2,-2.85 1.4,2.93, body extent -1.4,-2.85 1.4,2.85, height 2.51
SW_CAS-220TA [mm] "COPAL ELECTRONICS"
  rect 1.6x1 smd: 1(-1.85,1.75) 2(-1.85,0) 3(-1.85,-1.75) 4(1.85,1.75) 5(1.85,0) 6(1.85,-1.75)
  silkscreen extent -2.1,-2.9 2,3.7, body extent -2.1,-2.85 2.1,2.85, height 2.51
TE_640456-2 [mm] "Header, 2.54mm, 2x1, TH"
  rrect50% 1.55x1.55 hole 1.016: 1(-1.27,0)
  round 1.55 hole 1.016: 2(1.27,0)
  silkscreen extent -3.08,-3.27 2.64,2.77, body extent -2.54,-3.18 2.54,2.67, height 10.03
TE_RCU [mm] "SMD, 1-Leads, Body 1.6x0.8mm"
  rrect8% 2.4x1.2 smd: 1(0,0)
  body extent -0.8,-0.45 0.8,0.45, height 1.15
Testpoint_Keystone_Miniature [mil] "Miniature SMT test point"
  rrect1% 135x70 smd: 1(0,0)
  silkscreen extent -78,-46 78,45, body extent -52,-20 52,20, height 61
TI_Stacked_Overlay_Small [mm]
  silkscreen extent -10.63,-2.49 10.63,2.49
TSW-102-07-G-S [mm] "Samtec 100mil, 1x2, 230 mil above insulator"
  rrect50% 1.65x1.65 hole 1.016: 1(-1.27,0)
  round 1.65 hole 1.016: 2(1.27,0)
  silkscreen extent -3.17,-1.27 2.54,1.27, body extent -2.54,-1.27 2.54,1.27, height 8.38
WE-PMI_0603_L1.6W0.8H0.8 [mm] "Power Multilayer Inductor, body 1.6x0.8mm"
  rect 0.7x1 smd: 1(-0.8,0) 2(0.8,0)
  body extent -0.8,-0.4 0.8,0.4, height 0.8
WEEE_Minimum [mm] "WEEElie bin"
  silkscreen extent -2.42,-4.38 2.52,2.65
WL-SMCW_GREEN [mm] "WURTH"
  rect 0.8x0.8 smd: 1(-0.8,0) 2(0.8,0)
  silkscreen extent -1.9,-0.8 1.2,0.8, body extent -0.85,-0.45 0.85,0.45, height 0.8
WL-SMCW_RED [mm] "WURTH"
  rect 0.8x0.8 smd: 1(-0.8,0) 2(0.8,0)
  silkscreen extent -1.9,-0.8 1.2,0.8, body extent -0.85,-0.45 0.85,0.45, height 0.8
WURTH_61300311121 [mm] "Header, 2.54mm, 3x1, TH"
  rrect50% 1.65x1.65 hole 1.15: 1(-2.54,0)
  round 1.65 hole 1.15: 2(0,0) 3(2.54,0)
  body extent -3.81,-1.27 3.81,1.27, height 8.54
Wurth_618009231121 [mm] "Receptacle, D-Sub, 9 Position, R/A, TH"
  rect 1.5x1.5 hole 1: 1(-10.92,5.54)
  round 1.5 hole 1: 2(-10.92,2.77) 3(-10.92,0) 4(-10.92,-2.77) 5(-10.92,-5.54) 6(-8.08,4.155) 7(-8.08,1.385) 8(-8.08,-1.385) 9(-8.08,-4.155)
  round 3.7 hole 3.2: 10(-9.5,12.5) 11(-9.5,-12.5)
  silkscreen extent -12.78,-15.4 -0.53,15.4, body extent -12.5,-15.4 6,15.4, height 12.5

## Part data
"C1_Phase A" "C1_Phase B" "C1_Phase C": library part CMP-0006724-5, "CAP, CERM, 1000 pF, 100 V, +/- 10%, X7R, 0603", Cap_Case=0603, Manufacturer=AVX, Supplier Part Number 1=478-1199-1-ND, TempCo=X7R, Tolerance_%=10%, Value1="0.276 ohm", Value2=100V, ValueDisplayed=1000pF
C2 C3v3ldc C3v3ldc2 C4 C7 C9 "C10_Phase A" "C10_Phase B" "C10_Phase C" C15 C17 C18 C19 C20 C21 C22 C23 C24 C209 C210 C215 C216 C222 C234 C301 C302 C307 C308 C313 C314 C319 C325 C326 C335 C341 C342 C404 C406 C415 C421 C435 C502 C505 C517 C518 C600 C601 C602 C609 C611 C612 C901 C903 C905 C1300 C1301 Cu5c: library part CMP-0007078-4, "CAP, CERM, 0.1 uF, 50 V, +/- 10%, X7R, AEC-Q200 Grade 1, 0603", Cap_Case=0603, Manufacturer=TDK, Supplier Part Number 1=445-5666-1-ND, TempCo=X7R, Tolerance_%=10%, Value1="0.0296 ohm", Value2=50V, ValueDisplayed=0.1uF
C3: library part CMP-0086095-1, "CAP, CERM, 250 pF, 50 V,+/- 5%, C0G/NP0, 0603", Cap_Case=0603, Manufacturer=AVX, TempCo=C0G/NP0, Tolerance_%=5%, Value2=50V, ValueDisplayed=250pF
C3d1 C3d2 C6 C6n "C8_Phase A" "C8_Phase B" "C8_Phase C" "C14_Phase A" "C14_Phase B" "C14_Phase C": library part CMP-0046668-1, "10 pF ±10% 50V Ceramic Capacitor X7R 0603 (1608 Metric)", Digikey Part Number=478-11375-1-ND, Manufacturer="KYOCERA AVX", Mouser Part Number=581-06035C100KAT2A, Operating Temperature Range="-55°C to +125°C", TempCo=15%, Temperature Characteristic=X7R, Tolerance_%=10%, ValueDisplayed=10pF
C5 C238 C343 C444 C610: library part CMP-0860912-1, "CAP, CERM, 220 pF, 100 V,+/- 5%, C0G/NP0, AEC-Q200 Grade 1, 0603", Cap_Case=0603, Manufacturer=MuRata, TempCo=C0G/NP0, Tolerance_%=5%, Value2=100V, ValueDisplayed=220pF
"C11_Phase A" "C11_Phase B" "C11_Phase C" C906 C908: library part CMP-0079247-1, "CAP, CERM, 4700 pF, 100 V,+/- 10%, X7R, AEC-Q200 Grade 1, 0603", Cap_Case=0603, Manufacturer=MuRata, Supplier Part Number 1=490-4930-1-ND, TempCo=X7R, Tolerance_%=10%, Value2=100V, ValueDisplayed=4700pF
"C12_Phase A" "C12_Phase B" "C12_Phase C" "C13_Phase A" "C13_Phase B" "C13_Phase C" C16 C235 C337 C432 C907: library part CMP-0007075-4, "CAP, CERM, 100 pF, 50 V, +/- 5%, C0G/NP0, AEC-Q200 Grade 0, 0603", Cap_Case=0603, Manufacturer=TDK, Supplier Part Number 1=445-12386-1-ND, TempCo=C0G/NP0, Tolerance_%=5%, Value1=Unknown, Value2=50V, ValueDisplayed=100pF
C100 C101 C102: library part CMP-0008484-2, "CAP, CERM, 0.01 uF, 100 V, +/- 5%, X7R, 1206", Cap_Case=1206, Manufacturer=AVX, Supplier Part Number 1=478-3783-1-ND, TempCo=X7R, Tolerance_%=5%, Value1="0.119 ohm", Value2=100V, ValueDisplayed=0.01uF
C208 C211 C212 C213 C214 C217 C223 C224 C225 C300 C303 C304 C305 C306 C309 C320 C321 C322 C327 C339 C402 C407 C408 C409 C411 C416 C417 C418 C419 C423 C424 C425 C426 C427 C428 C430 C434 C437 C438 C439 C440 C441 C442 C504 C516: library part CMP-0007355-6, "CAP, CERM, 10 uF, 35 V, +/- 20%, X5R, 0603", Cap_Case=0603, Manufacturer=Murata, TempCo=X5R, Tolerance_%=20%, Value1=Unknown, Value2=35V, ValueDisplayed=10uF
C218 C221 C227 C310 C318 C328 C410 C414 C429 C503 C506 C510 C515 C909: library part CMP-0007082-4, "CAP, CERM, 0.01 uF, 100 V, +/- 10%, X7R, AEC-Q200 Grade 1, 0603", Cap_Case=0603, Manufacturer=TDK, Supplier Part Number 1=445-5812-1-ND, TempCo=X7R, Tolerance_%=10%, Value1="0.235428 ohm", Value2=100V, ValueDisplayed=0.01uF
C219 C316 C412 C431 C508 C512 C519 C521 C522 C523 C524 C525 C526 C527 C528 C530 C531: library part CMP-0006959-4, "CAP, CERM, 680 pF, 50 V, +/- 5%, C0G/NP0, 0603", Cap_Case=0603, Manufacturer=Kemet, Supplier Part Number 1=399-3289-1-ND, TempCo=C0G/NP0, Tolerance_%=5%, Value1=Unknown, Value2=50V, ValueDisplayed=680pF
C220 C317 C413 C501 C507 C509 C511 C513 C514 C520 C805 C808 C1000 C1001 C1002 C1302 C1303 C1304 C1305 C1306 C1307: library part CMP-0007173-4, "CAP, CERM, 1000 pF, 50 V, +/- 5%, C0G/NP0, 0603", Cap_Case=0603, Manufacturer=MuRata, Supplier Part Number 1=490-1451-1-ND, TempCo=C0G/NP0, Tolerance_%=5%, Value1=Unknown, Value2=50V, ValueDisplayed=1000pF
C226 C228 C323 C329: library part CMP-0085950-1, "CAP, CERM, 10 µF, 50 V,+/- 10%, X7R, AEC-Q200 Grade 1, 1206", Cap_Case=1206, Manufacturer=TDK, TempCo=X7R, Tolerance_%=10%, Value2=50V, ValueDisplayed=10µF
C229 C311 C324 C330 C340 C420 C422 C436 C804 C809: library part CMP-0007067-4, "CAP, CERM, 1 uF, 35 V, +/- 10%, X7R, AEC-Q200 Grade 1, 0603", Cap_Case=0603, Manufacturer=TDK, Supplier Part Number 1=445-174215-1-ND, TempCo=X7R, Tolerance_%=10%, Value1="0.005522 ohm", Value2=35V, ValueDisplayed=1uF
C230 C231 C232 C331 C332 C333 C345: library part CMP-0009226-3, "CAP, CERM, 10 uF, 50 V, +/- 10%, X7R, 1210", Cap_Case=1210, Manufacturer=MuRata, Supplier Part Number 1=490-6544-1-ND, TempCo=X7R, Tolerance_%=10%, Value1=Unknown, Value2=50V, ValueDisplayed=10uF
C233 C334: library part CMP-0007976-2, "CAP, CERM, 1 uF, 50 V, +/- 10%, X7R, AEC-Q200 Grade 1, 0805", Cap_Case=0805, Manufacturer=TDK, Supplier Part Number 1=445-6961-1-ND, TempCo=X7R, Tolerance_%=10%, Value1="0.008782 ohm", Value2=50V, ValueDisplayed=1uF
C236 C336 C433 C500: library part CMP-0007080-5, "CAP, CERM, 0.068 uF, 50 V, +/- 10%, X7R, AEC-Q200 Grade 1, 0603", Cap_Case=0603, Manufacturer=TDK, Supplier Part Number 1=445-5665-1-ND, TempCo=X7R, Tolerance_%=10%, Value1="0.035979 ohm", Value2=50V, ValueDisplayed=0.068uF
C237 C338 C443: library part CMP-0007079-4, "CAP, CERM, 0.047 uF, 50 V, +/- 10%, X7R, AEC-Q200 Grade 1, 0603", Cap_Case=0603, Manufacturer=TDK, Supplier Part Number 1=445-5664-1-ND, TempCo=X7R, Tolerance_%=10%, Value1="0.049007 ohm", Value2=50V, ValueDisplayed=0.047uF
C239 C312 C344 C445: library part CMP-0007140-4, "CAP, CERM, 0.22 uF, 25 V, +/- 10%, X7R, AEC-Q200 Grade 1, 0603", Cap_Case=0603, Manufacturer=MuRata, Supplier Part Number 1=490-4935-1-ND, TempCo=X7R, Tolerance_%=10%, Value1=Unknown, Value2=25V, ValueDisplayed=0.22uF
C315 C346: library part CMP-0009219-2, "CAP, CERM, 22 uF, 10 V, +/- 10%, X7R, 1210", Cap_Case=1210, Manufacturer=MuRata, Supplier Part Number 1=490-11653-1-ND, TempCo=X7R, Tolerance_%=10%, Value1="0.002 ohm", Value2=10V, ValueDisplayed=22uF
C603 C604: library part CMP-0007088-4, "CAP, CERM, 4700 pF, 100 V, +/- 10%, X7R, AEC-Q200 Grade 1, 0603", Cap_Case=0603, Manufacturer=TDK, Supplier Part Number 1=445-5810-1-ND, TempCo=X7R, Tolerance_%=10%, Value1="0.469862 ohm", Value2=100V, ValueDisplayed=4700pF
C605 C613 C614 C800 C801 C803: library part CMP-0090630-1, "0.015µF ±10% 50V Ceramic Capacitor X7R 0402 (1005 Metric)", Digikey Part Number=490-11956-1-ND, Manufacturer=Murata, Mouser Part Number=81-GCM155R71H153KA5D, Operating Temperature Range="-55°C to +125°C", TempCo=15%, Temperature Characteristic=X7R, Tolerance_%=10%, ValueDisplayed=15000pF
C606 C607 C802 C810: library part CMP-0079153-1, "CAP, CERM, 10 µF, 10 V,+/- 10%, X7R, AEC-Q200 Grade 1, 0805", Cap_Case=0805, Manufacturer=MuRata, Supplier Part Number 1=490-12646-1-ND, TempCo=X7R, Tolerance_%=10%, Value2=10V, ValueDisplayed=10µF
C608 C811: library part CMP-0081159-1, "CAP, CERM, 22 µF, 16 V,+/- 20%, X5R, 0603", Cap_Case=0603, Manufacturer=Samsung, Supplier Part Number 1=1276-7076-1-ND, TempCo=X5R, Tolerance_%=20%, Value2=16V, ValueDisplayed=22µF
C807: library part CMP-0007171-4, "CAP, CERM, 100 pF, 50 V, +/- 5%, C0G/NP0, 0603", Cap_Case=0603, Manufacturer=MuRata, Supplier Part Number 1=490-1427-1-ND, TempCo=C0G/NP0, Tolerance_%=5%, Value1=Unknown, Value2=50V, ValueDisplayed=100pF
C900 C902: library part CMP-0084284-1, "CAP, CERM, 2.2 µF, 10 V,+/- 10%, X7R, AEC-Q200 Grade 1, 0603", Cap_Case=0603, Manufacturer=MuRata, TempCo=X7R, Tolerance_%=10%, Value2=10V, ValueDisplayed=2.2µF
C904: library part CMP-0007486-5, "CAP, CERM, 680 pF, 100 V, +/- 10%, X7R, 0603", Cap_Case=0603, Manufacturer=MuRata, Supplier Part Number 1=490-1469-1-ND, TempCo=X7R, Tolerance_%=10%, Value1=Unknown, Value2=100V, ValueDisplayed=680pF
D1 D3: library part CMP-0002905-2, "LED, Green, SMD", Color=Green, Manufacturer="Wurth Elektronik", Value1=W, Value2=3.2V
D2: library part CMP-0002947-3, "LED, Red, SMD", Color=Red, Manufacturer="Wurth Elektronik", Power_TotalModule=72mW, Value1=0.072W, Value2=2V
D100: library part CMP-0006046-3, "Diode, TVS, Bi, 28 V, 45.4 Vc, SMB", Manufacturer="Diodes Inc.", Value1=600W
D202 D300 D401 D402: library part CMP-0028984-3, "Diode, Schottky, 60 V, 10 A, AEC-Q101, CFP15", Manufacturer=Nexperia, Value1=10A, Value2=0.56V
D500 D501 D502: library part CMP-0028604-2, "Diode, Schottky, 40 V, 0.2 A, SOT-363", Manufacturer="Micro Commercial Components", Value1=0.2A, Value2=1V
D600: library part CMP-0098376-1, "24-V, 1-Channel ESD Protection Diode", Breakdown Voltage=25.5V, Clamping Voltage=40V, Digikey Part Number=296-ESD1LIN24DYFRCT-ND, Manufacturer="Texas Instruments", Mouser Part Number=595-ESD1LIN24DYFR, Operating Temperature Range="-55°C to +150°C", ValueDisplayed=2.3pF
D602: library part CMP-0076974-2, "Diode, Switching, 100 V, 0.15 A, SOD-123", Manufacturer="Micro Commercial Components", Value1=0.15A, Value2=1.25V
D900: library part CMP-0028582-2, "Diode, Schottky, 20 V, 1 A, SMA", Manufacturer=Vishay-Semiconductor, Value1=1A, Value2=0.5V
FB600 FB601 FB800 FB801: library part CMP-0124053-1, "Ferrite Bead 600Ohm 0.9A 0.17Ohm Wirewound 2-Pin 0603 Paper T/R", Digikey Part Number=587-LCMGA160808T601RGCT-ND, Impedance At Frequency="600Ω @ 100MHz", Manufacturer="Taiyo Yuden", Mouser Part Number=963-LCMGA160808T601R, Operating Temperature Range="-40°C to +125°C", Tolerance_%=25%
FID1200 FID1201 FID1202 FID1203 FID1204 FID1205: library part CMP-0077181-1, "Fiducial mark.  There is nothing to buy or mount.", Manufacturer=N/A
J1 J2 "J3_Phase A" "J3_Phase B" "J3_Phase C" J12 J13 J500 J501 J502 J503 J504 J505 J506 J507 J508 J509 J510 J511 J512 J513 J514: library part CMP-0055256-1, "MMCX JACK, 50 Ohm, Gold, SMT", Color=Gold, Manufacturer=Molex, Supplier Part Number 1=WM3914CT-ND
J5 J10: library part CMP-0077643-1, "Header, 2.54mm, 2x1, Gold, TH", Color=Black, Current_A=5.7A, Manufacturer=Samtec, Supplier Part Number 1=SAM1038-02-ND, Voltage_V=550V
J6: library part CMP-02766-000359-1, "10 Position 2 Row .100\" (2.54 mm) pitch connector", Manufacturer=Samtec, Max Current Rating=7.4A, Max Operating Temperature=125°C, Max Voltage Rating (AC)=675V, Min Operating Temperature=-55°C
J7 J8 J9: library part CMP-0092858-1, "Connector Header Through Hole 3 position 0.100\" (2.54mm)", Current_A=4A, Digikey Part Number=WM4201-ND, Manufacturer=Molex, Mouser Part Number=538-22-23-2031, Operating Temperature Range=to, Voltage_V=500V
J11: library part CMP-0075601-2, "Header(Shrouded), 1.27mm, 6x2, Tin, SMT", Color=Black, Current_A=3.2A, Manufacturer=Samtec, Voltage_V=250V
J14 J15 J16: library part CMP-0056023-2, "Socket, 0.5MM, 60x2, Gold, SMT", Manufacturer=Samtec, Supplier Part Number 1=SAM8189-ND
J17 J18: library part CMP-0054796-4, "Header, 2.54 mm, 3x1, Gold, TH", Manufacturer="Wurth Elektronik", Supplier Part Number 1=732-5316-ND
J19 J20: library part CMP-0054552-2, "Header, 100mil, 3x2, Tin, TH", Color=Black, Current_A=3A, Manufacturer="Sullins Connector Solutions", Supplier Part Number 1=S2012E-03-ND, Voltage_V=1.8kV
J22: library part CMP-0055470-1, "Header, 2.54mm, 12x2, Gold, SMT", Color=Black, Manufacturer=Samtec, Supplier Part Number 1=78P3095, Voltage_V=475V
J23: library part CMP-0075437-2, "Header, 100mil, 5x2, Tin, SMT", Manufacturer=Samtec, Supplier Part Number 1=TSM-105-01-T-DV-P-ND
J24: library part CMP-0054738-2, "Header(shrouded), 2.54mm, 7x2, Gold, SMT", Color=Black, Current_A=3A, Manufacturer="Sullins Connector Solutions", Supplier Part Number 1=S9186-ND
J100: library part CMP-0075114-1, "Power Jack, 2mm, R/A, TH", Color=Black, Manufacturer="CUI Inc.", Supplier Part Number 1=CP-037AH-ND
J101: library part CMP-0097487-2, "9 Position D-Sub Plug, Male Pins Connector", Current_A=3A, Digikey Part Number=732-618009231221-ND, Manufacturer="Würth Elektronik", Mouser Part Number=710-618009231221, Operating Temperature Range="-55°C to +105°C", Voltage_V=125V
J102 J103: library part CMP-0054820-2, "Receptacle, D-Sub, 9 Position, R/A, TH", Color=Black, Current_A=3A, Manufacturer="Wurth Elektronik", Supplier Part Number 1=16T0655, Voltage_V=125V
